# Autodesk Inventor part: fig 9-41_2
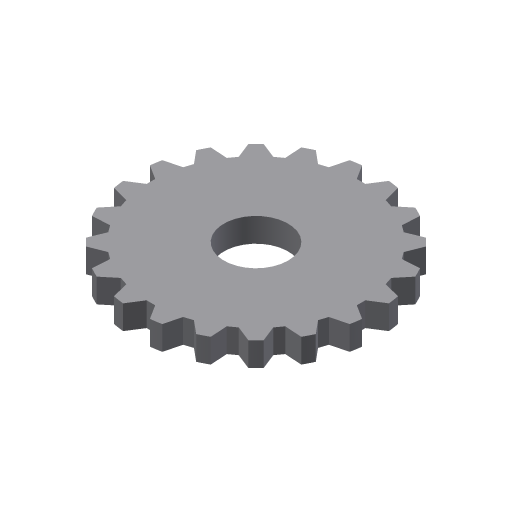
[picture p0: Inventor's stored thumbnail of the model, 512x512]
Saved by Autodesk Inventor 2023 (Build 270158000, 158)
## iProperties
Created: 2013-03
Part Number: fig 9-41_2
Material: Generic
Document SubType Name: Modeling
Designer: CADCIM
Density: 1 g/cm^3
Appearance: Default
Author: CADCIM
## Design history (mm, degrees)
sketch "Sketch1"
  geometry: C1 r 15 at (0, 0); C2 r 4 at (0, 0); 1 further point
  constraints: 2 centre point, 2 coincident
  dimensions: "d0" = 30 diameter of C1; "d2" = 8 diameter of C2
extrude "Extrusion1" new body sketch "Sketch1" distance "d3" = 3; taper "d4" = 0 deg
sketch "Sketch2"
  geometry: L1 (-1.675, 14.906)-(-0.536, 13.106); L2 (-0.536, 13.106)-(0.536, 13.106); L3 (0.536, 13.106)-(1.675, 14.906); L4 (0, 0)-(0, 16.254); C1 r 15 at (0, 0) reference; A1 r 15 centre (0, 0) between (1.675, 14.906) and (-1.675, 14.906); 2 further points
  constraints: 8 end point, 2 point on circle, 2 symmetric about line, 1 centre point, 1 coincident, 1 horizontal, 1 perpendicular
  dimensions: "d5" = 30 diameter of A1
extrude "Extrusion2" cut sketch "Sketch2" distance "d7" = 3; taper "d8" = 0 deg
body "Solid1"
pattern_circular "Circular Pattern1" dims angle "d10" = 360 deg
